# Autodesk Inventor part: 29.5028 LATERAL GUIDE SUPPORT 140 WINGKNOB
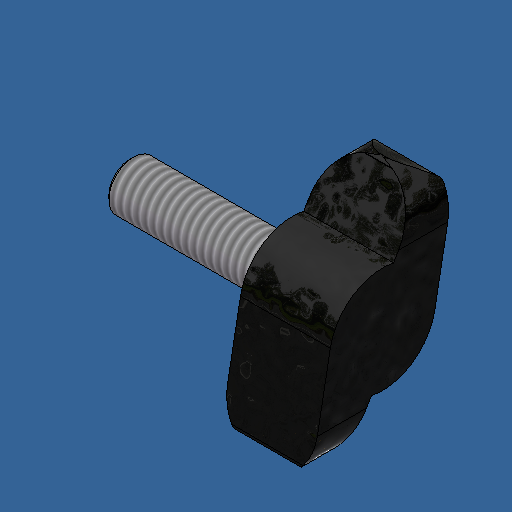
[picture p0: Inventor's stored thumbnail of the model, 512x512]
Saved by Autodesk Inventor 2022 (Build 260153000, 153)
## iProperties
Created: 2007-07
Part Number: 29.5028 LATERAL GUIDE SUPPORT 140 WINGKNOB
Material: ABS Plastic
Document SubType Name: Modeling
Designer: Andy Moles
Density: 1.06 g/cm^3
Appearance: Smooth - White
Author: Andy Moles
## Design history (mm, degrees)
feature "Base1"
thread "Thread1" dims "d0" = 10, "d1" = 0
chamfer "Chamfer1" distance "d2" = 0.5; stored, may be unused: second distance "d3" = 2, angle "d4" = 45 deg
body "Solid1"
